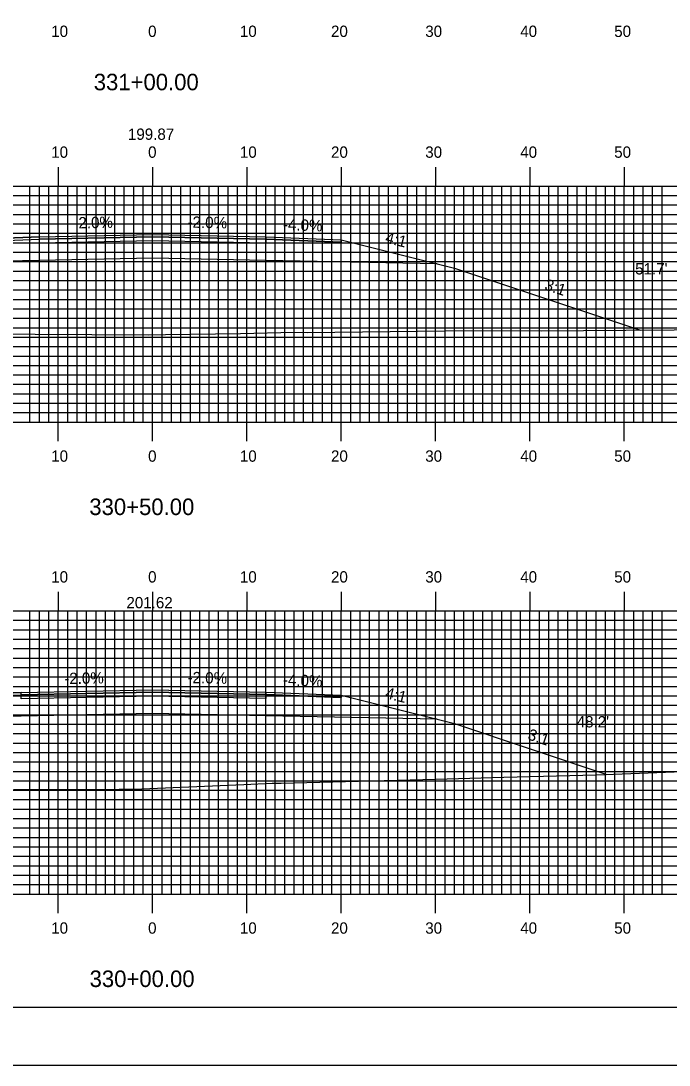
# Model space of a CAD drawing. Extents: x 1822392 to 1822735, y 442591 to 442811.
# Drawn here: x 1822543.8 to 1822612.5, y 442590.5 to 442701.2 of the extents above; entities that cross this region are included whole.
import ezdxf

# ---------------------------------------------------------------- set-up
doc = ezdxf.new("R2010")
doc.units = 0
for name, color, linetype in [('ANNOTATION', 7, 'Continuous'), ('BORDER', 7, 'Continuous'), ('D_Roadway_Centerline', 7, 'Continuous'), ('D_Roadway_Centerline_Text', 7, 'Continuous'), ('D_Roadway_Edge_Shoulder', 7, 'Continuous'), ('D_Roadway_Edge_TW', 7, 'Continuous'), ('D_Roadway_Pavement', 7, 'Continuous'), ('D_Roadway_SlopeLines', 7, 'Continuous'), ('D_Roadway_SubGrade', 7, 'Continuous'), ('D_Text_Standard', 7, 'Continuous'), ('H_V ANNOTATION', 7, 'Continuous'), ('MAJOR', 7, 'Continuous'), ('MINOR', 7, 'Continuous'), ('PLOT BOUNDARY', 7, 'Continuous'), ('S_Roadway_Centerline', 7, 'Continuous')]:
    doc.layers.add(name, color=color, linetype=linetype)

msp = doc.modelspace()

# ---------------------------------------------------------------- linework, layer by layer
at = {"layer": 'BORDER'}
msp.add_lwpolyline([(1822408.17, 442596.67), (1822728.17, 442596.67), (1822728.17, 442806.67), (1822408.17, 442806.67)], close=True, dxfattribs=at)
at = {"layer": 'D_Roadway_Centerline'}
for points in [[(1822503.81, 442667.66), (1822525.77, 442674.98), (1822527.6, 442675.44), (1822537.77, 442677.98), (1822545.77, 442678.3), (1822557.77, 442678.54), (1822569.77, 442678.3), (1822577.77, 442677.98), (1822587.94, 442675.44), (1822589.77, 442674.98), (1822609.48, 442668.41)], [(1822501.7, 442619.22), (1822524.16, 442626.7), (1822525.96, 442627.15), (1822536.16, 442629.7), (1822543.84, 442630.01), (1822557.77, 442630.29), (1822569.77, 442630.05), (1822577.77, 442629.73), (1822587.94, 442627.19), (1822589.77, 442626.73), (1822605.93, 442621.34)]]:
    msp.add_lwpolyline(points, dxfattribs=at)
at = {"layer": 'D_Roadway_Edge_Shoulder'}
for points in [[(1822545.77, 442678.3), (1822537.77, 442677.98), (1822537.77, 442677.73), (1822545.77, 442678.05)], [(1822569.77, 442678.3), (1822577.77, 442677.98), (1822577.77, 442677.73), (1822569.77, 442678.05)], [(1822543.84, 442630.01), (1822536.16, 442629.7), (1822536.16, 442629.45), (1822543.84, 442629.76)], [(1822569.77, 442630.05), (1822577.77, 442629.73), (1822577.77, 442629.48), (1822569.77, 442629.8)]]:
    msp.add_lwpolyline(points, close=True, dxfattribs=at)
at = {"layer": 'D_Roadway_Edge_TW'}
for points in [[(1822545.77, 442678.05), (1822545.77, 442678.3), (1822557.77, 442678.54), (1822569.77, 442678.3), (1822569.77, 442678.05), (1822557.77, 442678.29)], [(1822543.84, 442629.76), (1822543.84, 442630.01), (1822557.77, 442630.29), (1822569.77, 442630.05), (1822569.77, 442629.8), (1822557.77, 442630.04)]]:
    msp.add_lwpolyline(points, close=True, dxfattribs=at)
at = {"layer": 'D_Roadway_Pavement'}
for points in [[(1822545.77, 442677.63), (1822545.77, 442678.05), (1822557.77, 442678.29), (1822569.77, 442678.05), (1822569.77, 442677.63), (1822557.77, 442677.87)], [(1822543.84, 442629.34), (1822543.84, 442629.76), (1822557.77, 442630.04), (1822569.77, 442629.8), (1822569.77, 442629.38), (1822557.77, 442629.62)]]:
    msp.add_lwpolyline(points, close=True, dxfattribs=at)
at = {"layer": 'D_Roadway_SlopeLines'}
for points in [[(1822577.77, 442677.98), (1822589.77, 442674.98), (1822609.48, 442668.41)], [(1822577.77, 442629.73), (1822589.77, 442626.73), (1822605.93, 442621.34)]]:
    msp.add_lwpolyline(points, dxfattribs=at)
at = {"layer": 'D_Roadway_SubGrade'}
for points in [[(1822545.77, 442675.8), (1822527.6, 442675.44), (1822537.77, 442677.98), (1822537.77, 442677.73), (1822545.77, 442678.05), (1822557.77, 442678.29), (1822569.77, 442678.05), (1822577.77, 442677.73), (1822577.77, 442677.98), (1822587.94, 442675.44), (1822569.77, 442675.8), (1822557.77, 442676.04)], [(1822543.84, 442627.51), (1822525.96, 442627.15), (1822536.16, 442629.7), (1822536.16, 442629.45), (1822543.84, 442629.76), (1822557.77, 442630.04), (1822569.77, 442629.8), (1822577.77, 442629.48), (1822577.77, 442629.73), (1822587.94, 442627.19), (1822569.77, 442627.55), (1822557.77, 442627.79)]]:
    msp.add_lwpolyline(points, close=True, dxfattribs=at)
at = {"layer": 'MAJOR'}
for p, q in [((1822547.77, 442685.67), (1822547.77, 442683.67)), ((1822557.77, 442685.67), (1822557.77, 442683.67)), ((1822567.77, 442685.67), (1822567.77, 442683.67)), ((1822577.77, 442685.67), (1822577.77, 442683.67)), ((1822587.77, 442685.67), (1822587.77, 442683.67)), ((1822597.77, 442685.67), (1822597.77, 442683.67)), ((1822607.77, 442685.67), (1822607.77, 442683.67)), ((1822417.77, 442683.67), (1822697.77, 442683.67)), ((1822417.77, 442683.67), (1822697.77, 442683.67)), ((1822547.77, 442658.67), (1822547.77, 442683.67)), ((1822557.77, 442658.67), (1822557.77, 442683.67)), ((1822567.77, 442658.67), (1822567.77, 442683.67)), ((1822577.77, 442658.67), (1822577.77, 442683.67)), ((1822587.77, 442658.67), (1822587.77, 442683.67)), ((1822597.77, 442658.67), (1822597.77, 442683.67)), ((1822607.77, 442658.67), (1822607.77, 442683.67)), ((1822417.77, 442678.67), (1822697.77, 442678.67)), ((1822417.77, 442673.67), (1822697.77, 442673.67)), ((1822417.77, 442668.67), (1822697.77, 442668.67)), ((1822417.77, 442663.67), (1822697.77, 442663.67)), ((1822417.77, 442658.67), (1822697.77, 442658.67)), ((1822417.77, 442658.67), (1822697.77, 442658.67)), ((1822547.77, 442656.66), (1822547.77, 442658.67)), ((1822557.77, 442656.66), (1822557.77, 442658.67)), ((1822567.77, 442656.66), (1822567.77, 442658.67)), ((1822577.77, 442656.66), (1822577.77, 442658.67)), ((1822587.77, 442656.66), (1822587.77, 442658.67)), ((1822597.77, 442656.66), (1822597.77, 442658.67)), ((1822607.77, 442656.66), (1822607.77, 442658.67)), ((1822547.77, 442640.67), (1822547.77, 442638.67)), ((1822557.77, 442640.67), (1822557.77, 442638.67)), ((1822567.77, 442640.67), (1822567.77, 442638.67)), ((1822577.77, 442640.67), (1822577.77, 442638.67)), ((1822587.77, 442640.67), (1822587.77, 442638.67)), ((1822597.77, 442640.67), (1822597.77, 442638.67)), ((1822607.77, 442640.67), (1822607.77, 442638.67)), ((1822417.77, 442638.67), (1822697.77, 442638.67)), ((1822417.77, 442638.67), (1822697.77, 442638.67)), ((1822547.77, 442608.67), (1822547.77, 442638.67)), ((1822557.77, 442608.67), (1822557.77, 442638.67)), ((1822567.77, 442608.67), (1822567.77, 442638.67)), ((1822577.77, 442608.67), (1822577.77, 442638.67)), ((1822587.77, 442608.67), (1822587.77, 442638.67)), ((1822597.77, 442608.67), (1822597.77, 442638.67)), ((1822607.77, 442608.67), (1822607.77, 442638.67)), ((1822417.77, 442633.67), (1822697.77, 442633.67)), ((1822417.77, 442628.67), (1822697.77, 442628.67)), ((1822417.77, 442623.67), (1822697.77, 442623.67)), ((1822417.77, 442618.67), (1822697.77, 442618.67)), ((1822417.77, 442613.67), (1822697.77, 442613.67)), ((1822417.77, 442608.67), (1822697.77, 442608.67)), ((1822417.77, 442608.67), (1822697.77, 442608.67)), ((1822547.77, 442606.66), (1822547.77, 442608.67)), ((1822557.77, 442606.66), (1822557.77, 442608.67)), ((1822567.77, 442606.66), (1822567.77, 442608.67)), ((1822577.77, 442606.66), (1822577.77, 442608.67)), ((1822587.77, 442606.66), (1822587.77, 442608.67)), ((1822597.77, 442606.66), (1822597.77, 442608.67)), ((1822607.77, 442606.66), (1822607.77, 442608.67))]:
    msp.add_line(p, q, dxfattribs=at)
at = {"layer": 'MINOR'}
for p, q in [((1822544.77, 442658.67), (1822544.77, 442683.67)), ((1822545.77, 442658.67), (1822545.77, 442683.67)), ((1822546.77, 442658.67), (1822546.77, 442683.67)), ((1822548.77, 442658.67), (1822548.77, 442683.67)), ((1822549.77, 442658.67), (1822549.77, 442683.67)), ((1822550.77, 442658.67), (1822550.77, 442683.67)), ((1822551.77, 442658.67), (1822551.77, 442683.67)), ((1822552.77, 442658.67), (1822552.77, 442683.67)), ((1822553.77, 442658.67), (1822553.77, 442683.67)), ((1822554.77, 442658.67), (1822554.77, 442683.67)), ((1822555.77, 442658.67), (1822555.77, 442683.67)), ((1822556.77, 442658.67), (1822556.77, 442683.67)), ((1822558.77, 442658.67), (1822558.77, 442683.67)), ((1822559.77, 442658.67), (1822559.77, 442683.67)), ((1822560.77, 442658.67), (1822560.77, 442683.67)), ((1822561.77, 442658.67), (1822561.77, 442683.67)), ((1822562.77, 442658.67), (1822562.77, 442683.67)), ((1822563.77, 442658.67), (1822563.77, 442683.67)), ((1822564.77, 442658.67), (1822564.77, 442683.67)), ((1822565.77, 442658.67), (1822565.77, 442683.67)), ((1822566.77, 442658.67), (1822566.77, 442683.67)), ((1822568.77, 442658.67), (1822568.77, 442683.67)), ((1822569.77, 442658.67), (1822569.77, 442683.67)), ((1822570.77, 442658.67), (1822570.77, 442683.67)), ((1822571.77, 442658.67), (1822571.77, 442683.67)), ((1822572.77, 442658.67), (1822572.77, 442683.67)), ((1822573.77, 442658.67), (1822573.77, 442683.67)), ((1822574.77, 442658.67), (1822574.77, 442683.67)), ((1822575.77, 442658.67), (1822575.77, 442683.67)), ((1822576.77, 442658.67), (1822576.77, 442683.67)), ((1822578.77, 442658.67), (1822578.77, 442683.67)), ((1822579.77, 442658.67), (1822579.77, 442683.67)), ((1822580.77, 442658.67), (1822580.77, 442683.67)), ((1822581.77, 442658.67), (1822581.77, 442683.67)), ((1822582.77, 442658.67), (1822582.77, 442683.67)), ((1822583.77, 442658.67), (1822583.77, 442683.67)), ((1822584.77, 442658.67), (1822584.77, 442683.67)), ((1822585.77, 442658.67), (1822585.77, 442683.67)), ((1822586.77, 442658.67), (1822586.77, 442683.67)), ((1822588.77, 442658.67), (1822588.77, 442683.67)), ((1822589.77, 442658.67), (1822589.77, 442683.67)), ((1822590.77, 442658.67), (1822590.77, 442683.67)), ((1822591.77, 442658.67), (1822591.77, 442683.67)), ((1822592.77, 442658.67), (1822592.77, 442683.67)), ((1822593.77, 442658.67), (1822593.77, 442683.67)), ((1822594.77, 442658.67), (1822594.77, 442683.67)), ((1822595.77, 442658.67), (1822595.77, 442683.67)), ((1822596.77, 442658.67), (1822596.77, 442683.67)), ((1822598.77, 442658.67), (1822598.77, 442683.67)), ((1822599.77, 442658.67), (1822599.77, 442683.67)), ((1822600.77, 442658.67), (1822600.77, 442683.67)), ((1822601.77, 442658.67), (1822601.77, 442683.67)), ((1822602.77, 442658.67), (1822602.77, 442683.67)), ((1822603.77, 442658.67), (1822603.77, 442683.67)), ((1822604.77, 442658.67), (1822604.77, 442683.67)), ((1822605.77, 442658.67), (1822605.77, 442683.67)), ((1822606.77, 442658.67), (1822606.77, 442683.67)), ((1822608.77, 442658.67), (1822608.77, 442683.67)), ((1822609.77, 442658.67), (1822609.77, 442683.67)), ((1822610.77, 442658.67), (1822610.77, 442683.67)), ((1822611.77, 442658.67), (1822611.77, 442683.67)), ((1822417.77, 442682.67), (1822697.77, 442682.67)), ((1822417.77, 442681.67), (1822697.77, 442681.67)), ((1822417.77, 442680.67), (1822697.77, 442680.67)), ((1822417.77, 442679.67), (1822697.77, 442679.67)), ((1822417.77, 442677.67), (1822697.77, 442677.67)), ((1822417.77, 442676.67), (1822697.77, 442676.67)), ((1822417.77, 442675.67), (1822697.77, 442675.67)), ((1822417.77, 442674.67), (1822697.77, 442674.67)), ((1822417.77, 442672.67), (1822697.77, 442672.67)), ((1822417.77, 442671.67), (1822697.77, 442671.67)), ((1822417.77, 442670.67), (1822697.77, 442670.67)), ((1822417.77, 442669.67), (1822697.77, 442669.67)), ((1822417.77, 442667.67), (1822697.77, 442667.67)), ((1822417.77, 442666.67), (1822697.77, 442666.67)), ((1822417.77, 442665.67), (1822697.77, 442665.67)), ((1822417.77, 442664.67), (1822697.77, 442664.67)), ((1822417.77, 442662.67), (1822697.77, 442662.67)), ((1822417.77, 442661.67), (1822697.77, 442661.67)), ((1822417.77, 442660.67), (1822697.77, 442660.67)), ((1822417.77, 442659.67), (1822697.77, 442659.67)), ((1822544.77, 442608.67), (1822544.77, 442638.67)), ((1822545.77, 442608.67), (1822545.77, 442638.67)), ((1822546.77, 442608.67), (1822546.77, 442638.67)), ((1822548.77, 442608.67), (1822548.77, 442638.67)), ((1822549.77, 442608.67), (1822549.77, 442638.67)), ((1822550.77, 442608.67), (1822550.77, 442638.67)), ((1822551.77, 442608.67), (1822551.77, 442638.67)), ((1822552.77, 442608.67), (1822552.77, 442638.67)), ((1822553.77, 442608.67), (1822553.77, 442638.67)), ((1822554.77, 442608.67), (1822554.77, 442638.67)), ((1822555.77, 442608.67), (1822555.77, 442638.67)), ((1822556.77, 442608.67), (1822556.77, 442638.67)), ((1822558.77, 442608.67), (1822558.77, 442638.67)), ((1822559.77, 442608.67), (1822559.77, 442638.67)), ((1822560.77, 442608.67), (1822560.77, 442638.67)), ((1822561.77, 442608.67), (1822561.77, 442638.67)), ((1822562.77, 442608.67), (1822562.77, 442638.67)), ((1822563.77, 442608.67), (1822563.77, 442638.67)), ((1822564.77, 442608.67), (1822564.77, 442638.67)), ((1822565.77, 442608.67), (1822565.77, 442638.67)), ((1822566.77, 442608.67), (1822566.77, 442638.67)), ((1822568.77, 442608.67), (1822568.77, 442638.67)), ((1822569.77, 442608.67), (1822569.77, 442638.67)), ((1822570.77, 442608.67), (1822570.77, 442638.67)), ((1822571.77, 442608.67), (1822571.77, 442638.67)), ((1822572.77, 442608.67), (1822572.77, 442638.67)), ((1822573.77, 442608.67), (1822573.77, 442638.67)), ((1822574.77, 442608.67), (1822574.77, 442638.67)), ((1822575.77, 442608.67), (1822575.77, 442638.67)), ((1822576.77, 442608.67), (1822576.77, 442638.67)), ((1822578.77, 442608.67), (1822578.77, 442638.67)), ((1822579.77, 442608.67), (1822579.77, 442638.67)), ((1822580.77, 442608.67), (1822580.77, 442638.67)), ((1822581.77, 442608.67), (1822581.77, 442638.67)), ((1822582.77, 442608.67), (1822582.77, 442638.67)), ((1822583.77, 442608.67), (1822583.77, 442638.67)), ((1822584.77, 442608.67), (1822584.77, 442638.67)), ((1822585.77, 442608.67), (1822585.77, 442638.67)), ((1822586.77, 442608.67), (1822586.77, 442638.67)), ((1822588.77, 442608.67), (1822588.77, 442638.67)), ((1822589.77, 442608.67), (1822589.77, 442638.67)), ((1822590.77, 442608.67), (1822590.77, 442638.67)), ((1822591.77, 442608.67), (1822591.77, 442638.67)), ((1822592.77, 442608.67), (1822592.77, 442638.67)), ((1822593.77, 442608.67), (1822593.77, 442638.67)), ((1822594.77, 442608.67), (1822594.77, 442638.67)), ((1822595.77, 442608.67), (1822595.77, 442638.67)), ((1822596.77, 442608.67), (1822596.77, 442638.67)), ((1822598.77, 442608.67), (1822598.77, 442638.67)), ((1822599.77, 442608.67), (1822599.77, 442638.67)), ((1822600.77, 442608.67), (1822600.77, 442638.67)), ((1822601.77, 442608.67), (1822601.77, 442638.67)), ((1822602.77, 442608.67), (1822602.77, 442638.67)), ((1822603.77, 442608.67), (1822603.77, 442638.67)), ((1822604.77, 442608.67), (1822604.77, 442638.67)), ((1822605.77, 442608.67), (1822605.77, 442638.67)), ((1822606.77, 442608.67), (1822606.77, 442638.67)), ((1822608.77, 442608.67), (1822608.77, 442638.67)), ((1822609.77, 442608.67), (1822609.77, 442638.67)), ((1822610.77, 442608.67), (1822610.77, 442638.67)), ((1822611.77, 442608.67), (1822611.77, 442638.67)), ((1822417.77, 442637.67), (1822697.77, 442637.67)), ((1822417.77, 442636.67), (1822697.77, 442636.67)), ((1822417.77, 442635.67), (1822697.77, 442635.67)), ((1822417.77, 442634.67), (1822697.77, 442634.67)), ((1822417.77, 442632.67), (1822697.77, 442632.67)), ((1822417.77, 442631.67), (1822697.77, 442631.67)), ((1822417.77, 442630.67), (1822697.77, 442630.67)), ((1822417.77, 442629.67), (1822697.77, 442629.67)), ((1822417.77, 442627.67), (1822697.77, 442627.67)), ((1822417.77, 442626.67), (1822697.77, 442626.67)), ((1822417.77, 442625.67), (1822697.77, 442625.67)), ((1822417.77, 442624.67), (1822697.77, 442624.67)), ((1822417.77, 442622.67), (1822697.77, 442622.67)), ((1822417.77, 442621.67), (1822697.77, 442621.67)), ((1822417.77, 442620.67), (1822697.77, 442620.67)), ((1822417.77, 442619.67), (1822697.77, 442619.67)), ((1822417.77, 442617.67), (1822697.77, 442617.67)), ((1822417.77, 442616.67), (1822697.77, 442616.67)), ((1822417.77, 442615.67), (1822697.77, 442615.67)), ((1822417.77, 442614.67), (1822697.77, 442614.67)), ((1822417.77, 442612.67), (1822697.77, 442612.67)), ((1822417.77, 442611.67), (1822697.77, 442611.67)), ((1822417.77, 442610.67), (1822697.77, 442610.67)), ((1822417.77, 442609.67), (1822697.77, 442609.67))]:
    msp.add_line(p, q, dxfattribs=at)
at = {"layer": 'PLOT BOUNDARY'}
msp.add_lwpolyline([(1822391.98, 442590.55), (1822731.98, 442590.55), (1822731.98, 442810.55), (1822391.98, 442810.55)], close=True, dxfattribs=at)
at = {"layer": 'S_Roadway_Centerline'}
for points in [[(1822499.1, 442667.66), (1822505.18, 442667.66), (1822506.71, 442667.68), (1822518.67, 442667.81), (1822523.55, 442667.88), (1822532.01, 442667.94), (1822540.55, 442668.02), (1822545.31, 442667.99), (1822557.35, 442667.92), (1822559.14, 442667.94), (1822567.1, 442668.07), (1822572.77, 442668.18), (1822574.2, 442668.16), (1822577.09, 442668.19), (1822591.7, 442668.38), (1822598.94, 442668.35), (1822607.93, 442668.4), (1822623.32, 442668.51)], [(1822489.21, 442619.21), (1822502.32, 442619.22), (1822503.06, 442619.22), (1822503.33, 442619.22), (1822519.93, 442619.35), (1822529.66, 442619.54), (1822536.44, 442619.62), (1822543.04, 442619.73), (1822554.22, 442619.77), (1822556.61, 442619.81), (1822567.44, 442620.27), (1822570.44, 442620.4), (1822571.39, 442620.42), (1822587.8, 442620.85), (1822595, 442621.06), (1822604.77, 442621.3), (1822617.64, 442621.79)]]:
    msp.add_lwpolyline(points, dxfattribs=at)

# ---------------------------------------------------------------- texts
at = {"layer": 'ANNOTATION'}
for s, rotation, p in [('-2.0%', 1.1458, (1822549.38, 442679.17)), ('-2.0%', 358.8542, (1822561.46, 442679.27)), ('-4.0%', 357.7094, (1822571.56, 442679.03)), ('4:1', 345.9638, (1822582.36, 442677.69)), ('3:1', 341.5652, (1822599.23, 442672.73)), ('-2.0%', 1.1458, (1822548.41, 442630.9)), ('-2.0%', 358.8542, (1822561.46, 442631.02)), ('-4.0%', 357.7094, (1822571.56, 442630.78)), ('4:1', 345.9638, (1822582.36, 442629.44)), ('3:1', 341.5652, (1822597.45, 442625.08))]:
    msp.add_text(s, height=1.2, rotation=rotation, dxfattribs=at).set_placement(p)
at = {"layer": 'D_Roadway_Centerline'}
for s, p in [('C', (1822557.76, 442678.54)), ('L', (1822557.77, 442678.53)), ('C', (1822557.76, 442630.29)), ('L', (1822557.77, 442630.28))]:
    msp.add_text(s, height=0.0146, dxfattribs=at).set_placement(p)
at = {"layer": 'D_Roadway_Centerline_Text'}
for s, p in [('199.87', (1822555.15, 442688.57)), ('201.62', (1822554.99, 442638.94))]:
    msp.add_text(s, height=1.2, dxfattribs=at).set_placement(p)
at = {"layer": 'D_Text_Standard'}
for s, p in [("51.7'", (1822608.92, 442674.31)), ("48.2'", (1822602.72, 442626.32))]:
    msp.add_text(s, height=1.2, dxfattribs=at).set_placement(p)
at = {"layer": 'H_V ANNOTATION'}
for s, height, p in [('10', 1.2, (1822547.02, 442699.47)), ('0', 1.2, (1822557.29, 442699.47)), ('10', 1.2, (1822567.02, 442699.47)), ('20', 1.2, (1822576.68, 442699.47)), ('30', 1.2, (1822586.67, 442699.47)), ('40', 1.2, (1822596.74, 442699.47)), ('50', 1.2, (1822606.7, 442699.47)), ('331+00.00', 1.75, (1822551.53, 442693.82)), ('10', 1.2, (1822547.02, 442686.67)), ('0', 1.2, (1822557.29, 442686.67)), ('10', 1.2, (1822567.02, 442686.67)), ('20', 1.2, (1822576.68, 442686.67)), ('30', 1.2, (1822586.67, 442686.67)), ('40', 1.2, (1822596.74, 442686.67)), ('50', 1.2, (1822606.7, 442686.67)), ('10', 1.2, (1822547.02, 442654.47)), ('0', 1.2, (1822557.29, 442654.47)), ('10', 1.2, (1822567.02, 442654.47)), ('20', 1.2, (1822576.68, 442654.47)), ('30', 1.2, (1822586.67, 442654.47)), ('40', 1.2, (1822596.74, 442654.47)), ('50', 1.2, (1822606.7, 442654.47)), ('330+50.00', 1.75, (1822551.06, 442648.82)), ('10', 1.2, (1822547.02, 442641.67)), ('0', 1.2, (1822557.29, 442641.67)), ('10', 1.2, (1822567.02, 442641.67)), ('20', 1.2, (1822576.68, 442641.67)), ('30', 1.2, (1822586.67, 442641.67)), ('40', 1.2, (1822596.74, 442641.67)), ('50', 1.2, (1822606.7, 442641.67)), ('10', 1.2, (1822547.02, 442604.47)), ('0', 1.2, (1822557.29, 442604.47)), ('10', 1.2, (1822567.02, 442604.47)), ('20', 1.2, (1822576.68, 442604.47)), ('30', 1.2, (1822586.67, 442604.47)), ('40', 1.2, (1822596.74, 442604.47)), ('50', 1.2, (1822606.7, 442604.47)), ('330+00.00', 1.75, (1822551.09, 442598.82))]:
    msp.add_text(s, height=height, dxfattribs=at).set_placement(p)

doc.saveas('drawing.dxf')
